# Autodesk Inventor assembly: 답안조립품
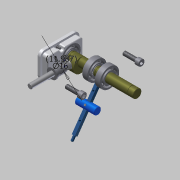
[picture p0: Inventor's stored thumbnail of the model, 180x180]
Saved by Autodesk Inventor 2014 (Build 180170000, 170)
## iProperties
Created: 2015-04
Part Number: 답안조립품
Document SubType Name: Assembly
Designer: Administrator
Author: Administrator
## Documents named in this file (15)
- C:\Documents and Settings\Administrator\바탕 화면\350406V1025\350406V1025\답안조립품.iam
- C:\Documents and Settings\Administrator\바탕 화면\350406V1025\350406V1025\본체.ipt
- C:\Documents and Settings\Administrator\바탕 화면\350406V1025\350406V1025\커버.ipt
- C:\Documents and Settings\Administrator\바탕 화면\350406V1025\350406V1025\M 10 x 35.ipt
- C:\Documents and Settings\Administrator\바탕 화면\350406V1025\350406V1025\커버2.ipt
- C:\Documents and Settings\Administrator\바탕 화면\350406V1025\350406V1025\M 5 x 12.ipt
- C:\Documents and Settings\Administrator\바탕 화면\350406V1025\350406V1025\베어링62_22.ipt
- C:\Documents and Settings\Administrator\바탕 화면\350406V1025\350406V1025\축.ipt
- C:\Documents and Settings\Administrator\바탕 화면\350406V1025\350406V1025\멈춤링.ipt
- C:\Documents and Settings\Administrator\바탕 화면\350406V1025\350406V1025\슬라이더3.ipt
- C:\Documents and Settings\Administrator\바탕 화면\350406V1025\350406V1025\부시.ipt
- C:\Documents and Settings\Administrator\바탕 화면\350406V1025\350406V1025\슬라이더2.ipt
- C:\Documents and Settings\Administrator\바탕 화면\350406V1025\350406V1025\슬라이더.ipt
- C:\Documents and Settings\Administrator\바탕 화면\350406V1025\350406V1025\가변스프링.ipt
- C:\Documents and Settings\Administrator\바탕 화면\350406V1025\350406V1025\평행핀.ipt
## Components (6 placed, 4 different names)
1. M 10 x 35:1
2. M 10 x 35:2
3. M 5 x 12:1
4. M 5 x 12:2
5. 가변스프링:1
6. KS B 1320 B B 5 x  20:1 — 플러쉬:1
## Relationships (1: Flush 1)
- 플러쉬:1 [Flush]: KS B 1320 B B 5 x  20:1
